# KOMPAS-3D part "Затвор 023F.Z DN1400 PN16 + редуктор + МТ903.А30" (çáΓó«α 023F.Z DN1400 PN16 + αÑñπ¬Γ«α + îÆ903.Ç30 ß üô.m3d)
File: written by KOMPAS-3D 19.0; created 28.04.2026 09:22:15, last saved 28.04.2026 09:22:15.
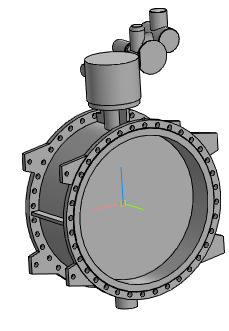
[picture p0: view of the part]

Document properties: Автор: Энергия; Полное имя файла: ..\Затвор 023F.Z DN1400 PN16 + редуктор + МТ903.А30.a3d

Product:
- Part/product: Затвор 023F.Z DN1400 PN16 + редуктор + МТ903.А30
    Масса: 3852.16

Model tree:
1. Операция без истории:1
